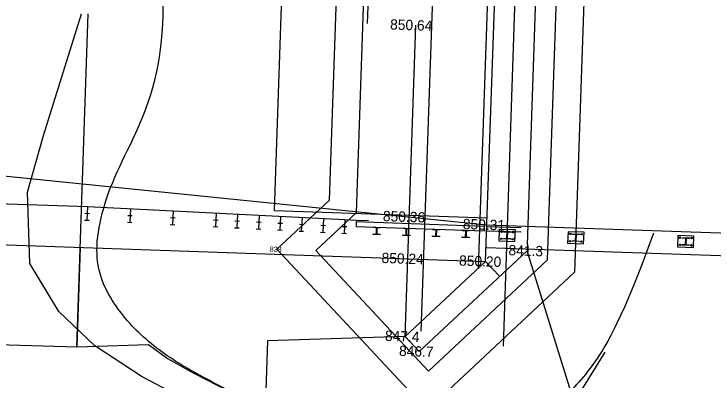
# Model space of a CAD drawing. Extents: x 2191309 to 2193046, y 863659 to 865133.
# Drawn here: x 2192617.6 to 2192668.4, y 863904.4 to 863931.1 of the extents above; entities that cross this region are included whole.
import ezdxf

# ---------------------------------------------------------------- set-up
doc = ezdxf.new("R2010")
doc.units = 0
for name, color, linetype in [('D_Bridge_Abutment', 7, 'Continuous'), ('D_Bridge_Deck', 7, 'Continuous'), ('D_Bridge_Railing', 7, 'Continuous'), ('D_Bridge_Substructure_Hidden', 7, 'Continuous'), ('D_Guardrail_Beam_Lt', 7, 'Continuous'), ('D_Guardrail_Beam_Rt', 7, 'Continuous'), ('D_Roadway_Edge_Shoulder', 7, 'Continuous'), ('D_Roadway_Edge_TW', 7, 'Continuous'), ('D_Slope_Direction', 7, 'Continuous'), ('D_Slope_Toe', 7, 'Continuous'), ('DIMENSIONS', 7, 'Continuous'), ('H_V CONTROLS', 7, 'Continuous'), ('JUNK', 7, 'Continuous')]:
    doc.layers.add(name, color=color, linetype=linetype)

msp = doc.modelspace()

# ---------------------------------------------------------------- linework, layer by layer
at = {"layer": 'D_Bridge_Abutment'}
for p, q in [((2192651.868, 863913.08), (2192653.034, 863947.06)), ((2192654.912, 863914.31), (2192654.896, 863913.856)), ((2192654.896, 863913.856), (2192647.044, 863906.524)), ((2192659.672, 863898.494), (2192654.896, 863913.856)), ((2192651.868, 863913.08), (2192646.02, 863907.621)), ((2192652.891, 863911.984), (2192651.868, 863913.08)), ((2192647.044, 863906.524), (2192646.02, 863907.621))]:
    msp.add_line(p, q, dxfattribs=at)
at = {"layer": 'D_Bridge_Deck'}
for p, q in [((2192651.959, 863915.745), (2192688.938, 863914.476)), ((2192651.902, 863914.08), (2192688.88, 863912.811))]:
    msp.add_line(p, q, dxfattribs=at)
at = {"layer": 'D_Bridge_Railing'}
for p, q in [((2192643.694, 863915.533), (2192643.695, 863915.571)), ((2192643.695, 863915.571), (2192644.201, 863915.553)), ((2192643.677, 863915.039), (2192643.678, 863915.077)), ((2192643.678, 863915.077), (2192643.888, 863915.07)), ((2192643.904, 863915.526), (2192643.694, 863915.533)), ((2192643.919, 863915.099), (2192643.933, 863915.495)), ((2192643.959, 863915.494), (2192643.946, 863915.098)), ((2192643.974, 863915.067), (2192644.185, 863915.06)), ((2192644.2, 863915.515), (2192643.99, 863915.523)), ((2192644.185, 863915.06), (2192644.183, 863915.022)), ((2192644.201, 863915.553), (2192644.2, 863915.515)), ((2192645.859, 863915.459), (2192645.861, 863915.496)), ((2192646.069, 863915.451), (2192645.859, 863915.459)), ((2192645.861, 863915.496), (2192646.367, 863915.479)), ((2192646.084, 863915.025), (2192646.098, 863915.421)), ((2192646.125, 863915.42), (2192646.111, 863915.024)), ((2192646.366, 863915.441), (2192646.155, 863915.448)), ((2192646.367, 863915.479), (2192646.366, 863915.441)), ((2192648.025, 863915.384), (2192648.026, 863915.422)), ((2192648.235, 863915.377), (2192648.025, 863915.384)), ((2192648.026, 863915.422), (2192648.532, 863915.405)), ((2192648.25, 863914.95), (2192648.263, 863915.346)), ((2192648.29, 863915.345), (2192648.276, 863914.949)), ((2192648.531, 863915.367), (2192648.321, 863915.374)), ((2192648.532, 863915.405), (2192648.531, 863915.367)), ((2192650.19, 863915.31), (2192650.191, 863915.348)), ((2192650.4, 863915.303), (2192650.19, 863915.31)), ((2192650.191, 863915.348), (2192650.698, 863915.33)), ((2192650.415, 863914.876), (2192650.429, 863915.272)), ((2192650.455, 863915.271), (2192650.442, 863914.875)), ((2192650.696, 863915.293), (2192650.486, 863915.3)), ((2192650.698, 863915.33), (2192650.696, 863915.293)), ((2192653.186, 863915.208), (2192653.188, 863915.245)), ((2192653.398, 863915.201), (2192653.186, 863915.208)), ((2192653.188, 863915.207), (2192653.19, 863915.245)), ((2192653.188, 863915.245), (2192653.698, 863915.227)), ((2192653.398, 863915.2), (2192653.188, 863915.207)), ((2192653.19, 863915.245), (2192653.696, 863915.227)), ((2192653.413, 863914.773), (2192653.427, 863915.169)), ((2192653.414, 863914.773), (2192653.427, 863915.169)), ((2192653.454, 863915.168), (2192653.44, 863914.772)), ((2192653.453, 863915.168), (2192653.44, 863914.772)), ((2192653.697, 863915.191), (2192653.485, 863915.198)), ((2192653.695, 863915.19), (2192653.485, 863915.197)), ((2192653.696, 863915.227), (2192653.695, 863915.19)), ((2192653.698, 863915.227), (2192653.697, 863915.191)), ((2192658.183, 863915.037), (2192658.185, 863915.073)), ((2192658.185, 863915.073), (2192658.695, 863915.056)), ((2192658.695, 863915.056), (2192658.694, 863915.019)), ((2192644.183, 863915.022), (2192643.677, 863915.039)), ((2192645.842, 863914.965), (2192645.844, 863915.003)), ((2192646.349, 863914.948), (2192645.842, 863914.965)), ((2192645.844, 863915.003), (2192646.054, 863914.996)), ((2192646.14, 863914.993), (2192646.35, 863914.986)), ((2192646.35, 863914.986), (2192646.349, 863914.948)), ((2192648.008, 863914.891), (2192648.009, 863914.929)), ((2192648.514, 863914.873), (2192648.008, 863914.891)), ((2192648.009, 863914.929), (2192648.219, 863914.921)), ((2192648.305, 863914.918), (2192648.515, 863914.911)), ((2192648.515, 863914.911), (2192648.514, 863914.873)), ((2192650.173, 863914.816), (2192650.174, 863914.854)), ((2192650.679, 863914.799), (2192650.173, 863914.816)), ((2192650.174, 863914.854), (2192650.384, 863914.847)), ((2192650.471, 863914.844), (2192650.681, 863914.837)), ((2192650.681, 863914.837), (2192650.679, 863914.799)), ((2192653.169, 863914.714), (2192653.171, 863914.75)), ((2192653.68, 863914.696), (2192653.169, 863914.714)), ((2192653.171, 863914.714), (2192653.173, 863914.751)), ((2192653.171, 863914.75), (2192653.382, 863914.743)), ((2192653.678, 863914.696), (2192653.171, 863914.714)), ((2192653.173, 863914.751), (2192653.383, 863914.744)), ((2192653.469, 863914.741), (2192653.679, 863914.734)), ((2192653.47, 863914.74), (2192653.681, 863914.733)), ((2192653.679, 863914.734), (2192653.678, 863914.696)), ((2192653.681, 863914.733), (2192653.68, 863914.696)), ((2192658.166, 863914.542), (2192658.168, 863914.579)), ((2192658.677, 863914.525), (2192658.166, 863914.542)), ((2192658.168, 863914.579), (2192658.379, 863914.572)), ((2192658.395, 863915.03), (2192658.183, 863915.037)), ((2192658.411, 863914.601), (2192658.424, 863914.998)), ((2192658.45, 863914.997), (2192658.437, 863914.601)), ((2192658.467, 863914.569), (2192658.678, 863914.561)), ((2192658.694, 863915.019), (2192658.482, 863915.027)), ((2192658.678, 863914.561), (2192658.677, 863914.525)), ((2192666.179, 863914.763), (2192666.18, 863914.799)), ((2192666.39, 863914.755), (2192666.179, 863914.763)), ((2192666.18, 863914.799), (2192666.69, 863914.782)), ((2192666.406, 863914.327), (2192666.42, 863914.723)), ((2192666.446, 863914.723), (2192666.432, 863914.326)), ((2192666.689, 863914.745), (2192666.478, 863914.752)), ((2192666.69, 863914.782), (2192666.689, 863914.745)), ((2192666.162, 863914.268), (2192666.163, 863914.305)), ((2192666.672, 863914.251), (2192666.162, 863914.268)), ((2192666.163, 863914.305), (2192666.374, 863914.297)), ((2192666.462, 863914.294), (2192666.673, 863914.287)), ((2192666.673, 863914.287), (2192666.672, 863914.251))]:
    msp.add_line(p, q, dxfattribs=at)
for points in [[(2192642.449, 863915.614), (2192651.777, 863915.293), (2192651.788, 863915.626), (2192642.461, 863915.947), (2192642.449, 863915.614)], [(2192654.448, 863915.202), (2192651.944, 863915.288), (2192651.955, 863915.621), (2192654.459, 863915.535)], [(2192652.86, 863915.256), (2192652.836, 863914.574), (2192654.002, 863914.534), (2192654.026, 863915.216)], [(2192654.026, 863915.216), (2192654.031, 863915.367), (2192652.865, 863915.407), (2192652.86, 863915.256)]]:
    msp.add_lwpolyline(points, dxfattribs=at)
for points in [[(2192652.836, 863914.574), (2192654.002, 863914.534), (2192654.031, 863915.367), (2192652.865, 863915.407)], [(2192657.833, 863914.403), (2192658.999, 863914.363), (2192659.028, 863915.196), (2192657.862, 863915.236)], [(2192665.829, 863914.128), (2192666.995, 863914.088), (2192667.023, 863914.921), (2192665.857, 863914.961)]]:
    msp.add_lwpolyline(points, close=True, dxfattribs=at)
for centre in [(2192653.026, 863915.25), (2192653.859, 863915.222), (2192658.023, 863915.079), (2192658.856, 863915.05), (2192653.008, 863914.72), (2192653.008, 863914.72), (2192653.841, 863914.691), (2192653.841, 863914.691), (2192658.005, 863914.548), (2192658.838, 863914.519), (2192666.019, 863914.805), (2192666.851, 863914.776), (2192666, 863914.274), (2192666.833, 863914.245)]:
    msp.add_circle(centre, 0.0521, dxfattribs=at)
for centre, radius, start, end in [((2192643.889, 863915.1), 0.0298, 268.0343, 358.0343), ((2192643.903, 863915.496), 0.0298, 358.0343, 88.0343), ((2192643.975, 863915.097), 0.0298, 178.0343, 268.0343), ((2192643.989, 863915.493), 0.0298, 88.0343, 178.0343), ((2192646.068, 863915.422), 0.0298, 358.0343, 88.0343), ((2192646.154, 863915.419), 0.0298, 88.0343, 178.0343), ((2192648.234, 863915.347), 0.0298, 358.0343, 88.0343), ((2192648.32, 863915.344), 0.0298, 88.0343, 178.0343), ((2192650.399, 863915.273), 0.0298, 358.0343, 88.0343), ((2192650.485, 863915.27), 0.0298, 88.0343, 178.0343), ((2192653.397, 863915.17), 0.0308, 358.0343, 88.0343), ((2192653.397, 863915.17), 0.0298, 358.0343, 88.0343), ((2192653.484, 863915.167), 0.0308, 88.0343, 178.0343), ((2192653.483, 863915.167), 0.0298, 88.0343, 178.0343), ((2192646.055, 863915.026), 0.0298, 268.0343, 358.0343), ((2192646.141, 863915.023), 0.0298, 178.0343, 268.0343), ((2192648.22, 863914.951), 0.0298, 268.0343, 358.0343), ((2192648.306, 863914.948), 0.0298, 178.0343, 268.0343), ((2192650.385, 863914.877), 0.0298, 268.0343, 358.0343), ((2192650.472, 863914.874), 0.0298, 178.0343, 268.0343), ((2192653.383, 863914.774), 0.0308, 268.0343, 358.0343), ((2192653.384, 863914.774), 0.0298, 268.0343, 358.0343), ((2192653.47, 863914.771), 0.0298, 178.0343, 268.0343), ((2192653.471, 863914.771), 0.0308, 178.0343, 268.0343), ((2192658.38, 863914.602), 0.0308, 268.0343, 358.0343), ((2192658.394, 863914.999), 0.0308, 358.0343, 88.0343), ((2192658.468, 863914.599), 0.0308, 178.0343, 268.0343), ((2192658.481, 863914.996), 0.0308, 88.0343, 178.0343), ((2192666.389, 863914.725), 0.0308, 358.0343, 88.0343), ((2192666.477, 863914.721), 0.0308, 88.0343, 178.0343), ((2192666.375, 863914.328), 0.0308, 268.0343, 358.0343), ((2192666.463, 863914.325), 0.0308, 178.0343, 268.0343)]:
    msp.add_arc(centre, radius, start, end, dxfattribs=at)
at = {"layer": 'D_Bridge_Substructure_Hidden'}
for p, q in [((2192651.351, 863912.598), (2192652.552, 863947.577)), ((2192656.374, 863913.183), (2192657.523, 863946.649)), ((2192654.912, 863914.31), (2192655.998, 863945.958)), ((2192642.484, 863916.632), (2192643.429, 863944.16)), ((2192642.484, 863916.632), (2192639.513, 863913.858)), ((2192647.702, 863905.087), (2192639.513, 863913.858)), ((2192656.374, 863913.183), (2192647.702, 863905.087))]:
    msp.add_line(p, q, dxfattribs=at)
msp.add_lwpolyline([(2192652.925, 863943.896), (2192637.435, 863944.427), (2192636.486, 863916.777), (2192651.976, 863916.245)], dxfattribs=at)
at = {"layer": 'D_Guardrail_Beam_Lt'}
for p, q in [((2192622.715, 863916.585), (2192623.048, 863916.568)), ((2192622.907, 863917.076), (2192622.856, 863916.077)), ((2192622.907, 863917.076), (2192629.149, 863916.755)), ((2192626.028, 863916.916), (2192625.977, 863915.917)), ((2192629.149, 863916.755), (2192629.098, 863915.757)), ((2192629.149, 863916.755), (2192641.633, 863916.114)), ((2192632.27, 863916.595), (2192632.219, 863915.596)), ((2192622.69, 863916.086), (2192623.022, 863916.069)), ((2192625.836, 863916.425), (2192626.169, 863916.408)), ((2192628.957, 863916.265), (2192629.29, 863916.248)), ((2192632.078, 863916.104), (2192632.411, 863916.087)), ((2192633.83, 863916.515), (2192633.779, 863915.516)), ((2192635.391, 863916.435), (2192635.34, 863915.436)), ((2192636.951, 863916.355), (2192636.9, 863915.356)), ((2192638.512, 863916.274), (2192638.46, 863915.276)), ((2192640.072, 863916.194), (2192640.021, 863915.196)), ((2192641.633, 863916.114), (2192641.581, 863915.115)), ((2192641.633, 863916.114), (2192642.465, 863916.071)), ((2192642.465, 863916.071), (2192643.36, 863916.041)), ((2192625.81, 863915.926), (2192626.143, 863915.909)), ((2192628.931, 863915.765), (2192629.264, 863915.748)), ((2192632.052, 863915.605), (2192632.385, 863915.588)), ((2192633.638, 863916.024), (2192633.971, 863916.007)), ((2192635.199, 863915.944), (2192635.532, 863915.927)), ((2192636.759, 863915.864), (2192637.092, 863915.847)), ((2192638.32, 863915.784), (2192638.653, 863915.767)), ((2192639.88, 863915.703), (2192640.213, 863915.686)), ((2192641.441, 863915.623), (2192641.773, 863915.606)), ((2192633.613, 863915.525), (2192633.946, 863915.508)), ((2192635.173, 863915.445), (2192635.506, 863915.428)), ((2192636.734, 863915.364), (2192637.066, 863915.347)), ((2192638.294, 863915.284), (2192638.627, 863915.267)), ((2192639.854, 863915.204), (2192640.187, 863915.187)), ((2192641.415, 863915.124), (2192641.748, 863915.107))]:
    msp.add_line(p, q, dxfattribs=at)
for centre, start, end in [((2192653.026, 863915.25), 358.0343, 178.0343), ((2192653.026, 863915.25), 178.0343, 358.0343), ((2192653.859, 863915.222), 358.0343, 178.0343), ((2192653.859, 863915.222), 178.0343, 358.0343)]:
    msp.add_arc(centre, 0.0521, start, end, dxfattribs=at)
at = {"layer": 'D_Guardrail_Beam_Rt'}
msp.add_line((2192551.075, 863919.542), (2192622.907, 863917.076), dxfattribs=at)
at = {"layer": 'D_Roadway_Edge_Shoulder'}
msp.add_line((2192550.972, 863916.543), (2192651.868, 863913.08), dxfattribs=at)
at = {"layer": 'D_Roadway_Edge_TW'}
msp.add_lwpolyline([(2192472.667, 863924.871), (2192497.665, 863924.377), (2192602.214, 863920.788), (2192651.959, 863915.745)], dxfattribs=at)
at = {"layer": 'D_Slope_Direction'}
msp.add_line((2192622.385, 863914.092), (2192622.137, 863906.858), dxfattribs=at)
at = {"layer": 'D_Slope_Toe'}
msp.add_line((2192659.672, 863898.494), (2192654.896, 863913.856), dxfattribs=at)
for points in [[(2192654.896, 863913.856), (2192647.044, 863906.524), (2192646.02, 863907.621), (2192636, 863907.301), (2192635.435, 863890.838)], [(2192517.468, 863911.436), (2192522.197, 863910.325), (2192537.377, 863906.759), (2192546.93, 863902.105), (2192572.068, 863905.706), (2192575.355, 863906.176), (2192575.844, 863906.154), (2192597.125, 863906.954), (2192613.89, 863907.091), (2192622.137, 863906.858), (2192627.35, 863907.024), (2192628.724, 863906.006), (2192630.643, 863904.932), (2192635.827, 863902.277)]]:
    msp.add_lwpolyline(points, dxfattribs=at)
at = {"layer": 'DIMENSIONS'}
msp.add_line((2192653.157, 863906.91), (2192656.738, 864011.242), dxfattribs=at)
at = {"layer": 'H_V CONTROLS'}
msp.add_line((2192646.02, 863907.621), (2192646.797, 863930.264), dxfattribs=at)
at = {"layer": 'JUNK'}
for p, q in [((2192647.954, 863930.225), (2192648.934, 863958.793)), ((2192643.726, 863943.842), (2192643.264, 863930.386)), ((2192640.514, 863917.529), (2192641.402, 863943.401)), ((2192622.137, 863906.858), (2192622.968, 863931.082)), ((2192647.191, 863908.01), (2192647.954, 863930.225)), ((2192640.514, 863917.529), (2192636.686, 863913.955))]:
    msp.add_line(p, q, dxfattribs=at)
for points in [[(2192637.828, 863947.229), (2192649.523, 863958.147), (2192659.55, 863947.408), (2192658.344, 863912.287), (2192647.605, 863902.26), (2192636.686, 863913.955)], [(2192636.839, 863896.208), (2192634.583, 863900.089), (2192630.873, 863902.598), (2192626.884, 863904.672), (2192623.432, 863906.932), (2192620.816, 863909.439), (2192618.716, 863912.913), (2192618.547, 863918.11), (2192619.713, 863922.238), (2192622.469, 863931.099)], [(2192654.615, 863888.999), (2192655.146, 863891.063), (2192655.367, 863893.109), (2192655.367, 863895.142), (2192655.346, 863897.174), (2192657.105, 863900.869), (2192660.561, 863906.471)]]:
    msp.add_lwpolyline(points, dxfattribs=at)
msp.add_open_spline([(2192664.087, 863915.13), (2192661.833, 863908.973), (2192659.632, 863905.174), (2192657.321, 863902.93), (2192654.418, 863900.048), (2192652.473, 863897.638), (2192650.675, 863895.417), (2192648.365, 863894.638), (2192644.671, 863895.34), (2192641.195, 863897.953), (2192634.581, 863903.022), (2192630.83, 863904.841), (2192627.384, 863906.997), (2192624.834, 863909.746), (2192623.07, 863913.243), (2192624.488, 863919.117), (2192628.399, 863925.562), (2192628.765, 863936.224), (2192624.451, 863946.4), (2192626.793, 863953.699), (2192629.251, 863955.168), (2192632.124, 863956.268), (2192636.17, 863957.994), (2192640.744, 863960.211), (2192647.549, 863963.813), (2192664.087, 863915.13), (2192647.549, 863963.813)], degree=3, dxfattribs=at)

# ---------------------------------------------------------------- texts
for s, height, p in [('850.64', 0.75, (2192644.913, 863929.954)), ('850.36', 0.75, (2192644.387, 863916.008)), ('850.31', 0.75, (2192650.202, 863915.431)), ('838', 0.375, (2192636.16, 863913.786)), ('841.3', 0.75, (2192653.523, 863913.528)), ('850.24', 0.75, (2192644.289, 863912.965)), ('850.20', 0.75, (2192649.929, 863912.772)), ('847.4', 0.75, (2192644.537, 863907.297)), ('846.7', 0.75, (2192645.56, 863906.2))]:
    msp.add_text(s, height=height, rotation=358.0343, dxfattribs=at).set_placement(p)

doc.saveas('drawing.dxf')
